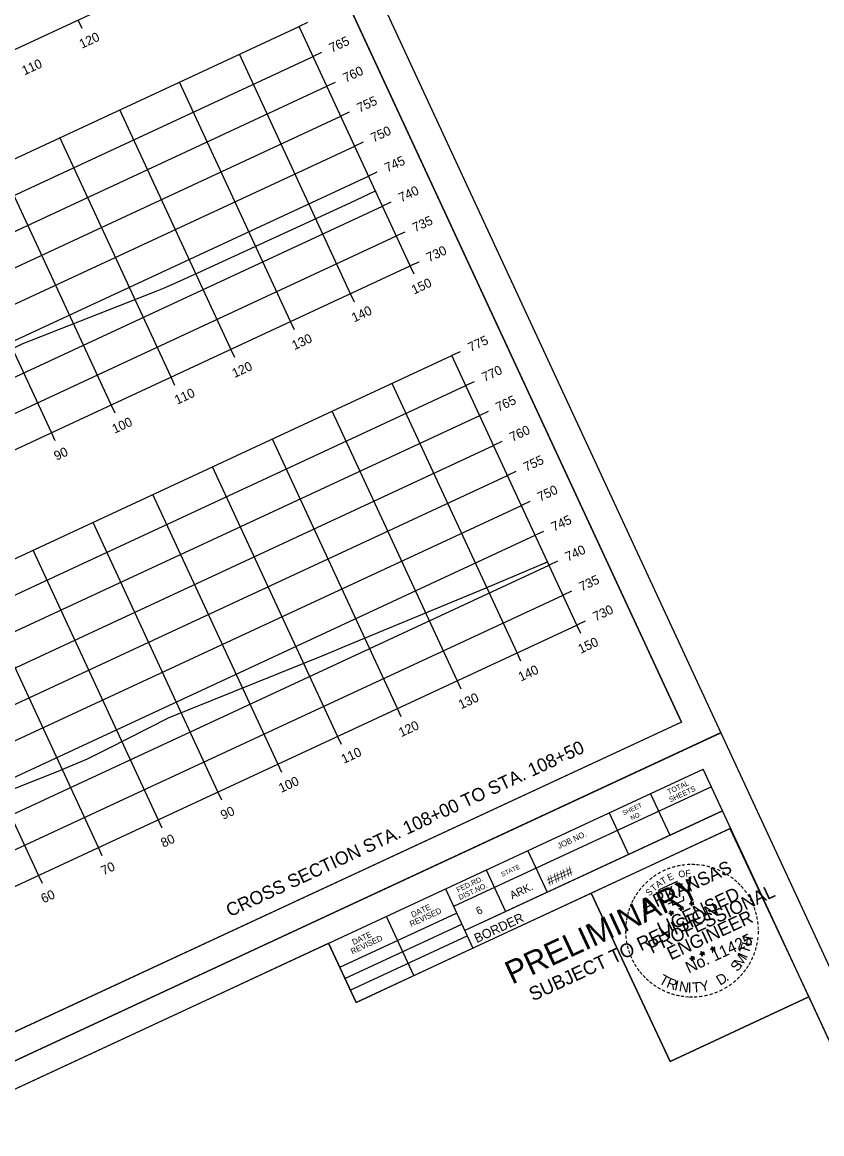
# Model space of a CAD drawing. Extents: x 1354696 to 1366163, y 660729 to 670380.
# Drawn here: x 1355072 to 1355193.2, y 664952.5 to 665120.9 of the extents above; entities that cross this region are included whole.
import ezdxf

# ---------------------------------------------------------------- set-up
doc = ezdxf.new("R2010")
doc.units = 0
for name, color, linetype in [('R_Axis', 7, 'Continuous'), ('R_Axis Annot', 7, 'Continuous'), ('R_Border', 7, 'Continuous'), ('R_Border PE', 7, 'Continuous'), ('R_Border Prem', 7, 'Continuous'), ('R_Draft', 7, 'Continuous'), ('R_Exist Surface', 7, 'Continuous'), ('R_Grid', 7, 'Continuous'), ('R_No Plot', 7, 'Continuous')]:
    doc.layers.add(name, color=color, linetype=linetype)

msp = doc.modelspace()

# ---------------------------------------------------------------- linework, layer by layer
at = {"layer": 'R_Axis'}
for p, q in [((1354835.56, 665007.58), (1355107.67, 665133.91)), ((1355081.05, 665120.01), (1355080.46, 665121.27)), ((1355115.25, 665120.89), (1355113.98, 665120.3)), ((1355130.83, 665084.02), (1355113.98, 665120.3)), ((1355117.36, 665116.36), (1355116.09, 665115.77)), ((1355119.46, 665111.82), (1355118.19, 665111.23)), ((1355121.57, 665107.29), (1355120.3, 665106.7)), ((1355123.68, 665102.75), (1355122.41, 665102.16)), ((1355125.78, 665098.22), (1355124.51, 665097.63)), ((1355127.89, 665093.68), (1355126.62, 665093.09)), ((1355129.99, 665089.15), (1355128.72, 665088.56)), ((1354858.72, 664957.69), (1355130.83, 665084.02)), ((1355132.1, 665084.61), (1355130.83, 665084.02)), ((1355131.42, 665082.75), (1355130.83, 665084.02)), ((1355122.35, 665078.54), (1355121.76, 665079.81)), ((1355113.28, 665074.33), (1355112.69, 665075.6)), ((1355104.21, 665070.12), (1355103.62, 665071.39)), ((1355138.41, 665071.01), (1355137.14, 665070.42)), ((1355156.09, 665029.6), (1355137.14, 665070.42)), ((1355095.14, 665065.91), (1355094.55, 665067.18)), ((1355140.52, 665066.47), (1355139.25, 665065.88)), ((1355086.07, 665061.7), (1355085.48, 665062.97)), ((1355142.63, 665061.94), (1355141.36, 665061.35)), ((1355077, 665057.49), (1355076.41, 665058.76)), ((1355144.73, 665057.4), (1355143.46, 665056.81)), ((1355146.84, 665052.87), (1355145.57, 665052.28)), ((1355148.94, 665048.33), (1355147.67, 665047.74)), ((1355151.05, 665043.8), (1355149.78, 665043.21)), ((1355153.15, 665039.26), (1355151.88, 665038.67)), ((1355155.26, 665034.73), (1355153.99, 665034.14)), ((1354883.99, 664903.27), (1355156.09, 665029.6)), ((1355157.36, 665030.19), (1355156.09, 665029.6)), ((1355156.68, 665028.33), (1355156.09, 665029.6)), ((1355147.61, 665024.12), (1355147.02, 665025.39)), ((1355138.54, 665019.91), (1355137.95, 665021.18)), ((1355129.47, 665015.7), (1355128.88, 665016.97)), ((1355120.4, 665011.49), (1355119.81, 665012.76)), ((1355111.33, 665007.28), (1355110.74, 665008.55)), ((1355102.26, 665003.07), (1355101.67, 665004.34)), ((1355093.19, 664998.85), (1355092.6, 665000.12)), ((1355084.12, 664994.64), (1355083.53, 664995.91)), ((1355075.05, 664990.43), (1355074.46, 664991.7))]:
    msp.add_line(p, q, dxfattribs=at)
at = {"layer": 'R_Border'}
for p, q in [((1355171.94, 665014.91), (1355085.42, 665201.26)), ((1355171.94, 665014.91), (1354885.16, 664881.76)), ((1354888.47, 664874.62), (1355175.25, 665007.76)), ((1355261.77, 664821.41), (1355175.25, 665007.76)), ((1355176.49, 665005.09), (1355137.4, 664986.94)), ((1355167.27, 665004.05), (1355170.19, 664997.76)), ((1355176.48, 665005.11), (1355176.48, 665005.11)), ((1355178.18, 665001.47), (1355139.08, 664983.32)), ((1355141.77, 664984.56), (1355178.18, 665001.47)), ((1355160.98, 665001.13), (1355163.9, 664994.84)), ((1355179.41, 664998.8), (1355122.6, 664972.42)), ((1355148.66, 664995.41), (1355151.58, 664989.12)), ((1355142.36, 664992.49), (1355145.29, 664986.2)), ((1355136.16, 664989.61), (1355140.32, 664980.65)), ((1355120.13, 664977.74), (1355137.85, 664985.96)), ((1355131.38, 664976.5), (1355127.22, 664985.46)), ((1355120.91, 664976.05), (1355138.64, 664984.28)), ((1355121.73, 664974.29), (1355139.45, 664982.52)), ((1355122.6, 664972.42), (1355118.44, 664981.38))]:
    msp.add_line(p, q, dxfattribs=at)
at = {"layer": 'R_Border PE'}
for p, q in [((1355173.17, 664987.35), (1355173.42, 664987.42)), ((1355173.17, 664987.35), (1355173.54, 664987.4)), ((1355173.17, 664987.35), (1355173.44, 664987.34)), ((1355173.54, 664987.4), (1355173.38, 664987.73)), ((1355173.38, 664987.73), (1355173.53, 664987.52)), ((1355173.38, 664987.73), (1355173.45, 664987.48)), ((1355173.47, 664987.04), (1355173.54, 664987.4)), ((1355173.47, 664987.04), (1355173.57, 664987.32)), ((1355173.47, 664987.04), (1355173.48, 664987.31)), ((1355173.8, 664987.64), (1355173.54, 664987.4)), ((1355173.85, 664987.22), (1355173.54, 664987.4)), ((1355173.8, 664987.64), (1355173.57, 664987.48)), ((1355173.85, 664987.22), (1355173.57, 664987.32)), ((1355173.85, 664987.22), (1355173.61, 664987.42)), ((1355173.8, 664987.64), (1355173.66, 664987.46)), ((1355170.05, 664985.91), (1355170.3, 664985.98)), ((1355170.05, 664985.91), (1355170.42, 664985.96)), ((1355170.05, 664985.91), (1355170.32, 664985.9)), ((1355170.42, 664985.96), (1355170.26, 664986.29)), ((1355170.26, 664986.29), (1355170.41, 664986.09)), ((1355170.26, 664986.29), (1355170.33, 664986.05)), ((1355170.35, 664985.6), (1355170.42, 664985.96)), ((1355170.35, 664985.6), (1355170.45, 664985.89)), ((1355170.35, 664985.6), (1355170.36, 664985.88)), ((1355170.68, 664986.21), (1355170.42, 664985.96)), ((1355170.73, 664985.78), (1355170.42, 664985.96)), ((1355170.68, 664986.21), (1355170.45, 664986.04)), ((1355170.73, 664985.78), (1355170.45, 664985.88)), ((1355170.73, 664985.78), (1355170.49, 664985.99)), ((1355170.68, 664986.21), (1355170.54, 664986.03)), ((1355171.57, 664986.62), (1355171.82, 664986.68)), ((1355171.57, 664986.62), (1355171.93, 664986.66)), ((1355171.57, 664986.62), (1355171.83, 664986.61)), ((1355171.93, 664986.66), (1355171.78, 664987)), ((1355171.78, 664987), (1355171.93, 664986.79)), ((1355171.78, 664987), (1355171.85, 664986.75)), ((1355171.86, 664986.3), (1355171.93, 664986.66)), ((1355171.86, 664986.3), (1355171.96, 664986.59)), ((1355171.86, 664986.3), (1355171.87, 664986.58)), ((1355172.2, 664986.91), (1355171.93, 664986.66)), ((1355172.25, 664986.48), (1355171.93, 664986.66)), ((1355172.2, 664986.91), (1355171.96, 664986.75)), ((1355172.25, 664986.48), (1355171.96, 664986.59)), ((1355172.25, 664986.48), (1355172, 664986.69)), ((1355172.2, 664986.91), (1355172.06, 664986.73)), ((1355176.36, 664980.48), (1355176.61, 664980.55)), ((1355176.36, 664980.48), (1355176.72, 664980.53)), ((1355176.36, 664980.48), (1355176.63, 664980.47)), ((1355176.72, 664980.53), (1355176.57, 664980.86)), ((1355176.57, 664980.86), (1355176.72, 664980.65)), ((1355176.57, 664980.86), (1355176.64, 664980.61)), ((1355176.65, 664980.17), (1355176.72, 664980.53)), ((1355176.65, 664980.17), (1355176.75, 664980.45)), ((1355176.65, 664980.17), (1355176.66, 664980.44)), ((1355176.99, 664980.78), (1355176.72, 664980.53)), ((1355177.04, 664980.35), (1355176.72, 664980.53)), ((1355176.99, 664980.78), (1355176.75, 664980.61)), ((1355177.04, 664980.35), (1355176.76, 664980.45)), ((1355177.04, 664980.35), (1355176.79, 664980.55)), ((1355176.99, 664980.78), (1355176.85, 664980.6)), ((1355173.24, 664979.04), (1355173.49, 664979.11)), ((1355173.24, 664979.04), (1355173.6, 664979.09)), ((1355173.24, 664979.04), (1355173.51, 664979.03)), ((1355173.6, 664979.09), (1355173.45, 664979.42)), ((1355173.45, 664979.42), (1355173.6, 664979.22)), ((1355173.45, 664979.42), (1355173.52, 664979.18)), ((1355173.53, 664978.73), (1355173.6, 664979.09)), ((1355173.53, 664978.73), (1355173.63, 664979.02)), ((1355173.53, 664978.73), (1355173.54, 664979)), ((1355173.87, 664979.34), (1355173.6, 664979.09)), ((1355173.92, 664978.91), (1355173.6, 664979.09)), ((1355173.87, 664979.34), (1355173.63, 664979.17)), ((1355173.92, 664978.91), (1355173.64, 664979.01)), ((1355173.92, 664978.91), (1355173.67, 664979.12)), ((1355173.87, 664979.34), (1355173.73, 664979.16)), ((1355174.75, 664979.75), (1355175, 664979.81)), ((1355174.75, 664979.75), (1355175.12, 664979.79)), ((1355174.75, 664979.75), (1355175.02, 664979.74)), ((1355175.12, 664979.79), (1355174.96, 664980.12)), ((1355174.96, 664980.12), (1355175.11, 664979.92)), ((1355174.96, 664980.12), (1355175.03, 664979.88)), ((1355175.04, 664979.43), (1355175.12, 664979.79)), ((1355175.04, 664979.43), (1355175.15, 664979.72)), ((1355175.04, 664979.43), (1355175.06, 664979.71)), ((1355175.38, 664980.04), (1355175.12, 664979.79)), ((1355175.43, 664979.61), (1355175.12, 664979.79)), ((1355175.38, 664980.04), (1355175.15, 664979.88)), ((1355175.43, 664979.61), (1355175.15, 664979.72)), ((1355175.43, 664979.61), (1355175.19, 664979.82)), ((1355175.38, 664980.04), (1355175.24, 664979.86))]:
    msp.add_line(p, q, dxfattribs=at)
for points in [[(1355172.03, 664990.09), (1355172.04, 664990.41), (1355171.43, 664990.1), (1355171.28, 664990.76), (1355168.46, 664989.45)], [(1355168.46, 664989.45), (1355169.05, 664988.81)], [(1355169.92, 664987.46), (1355169.96, 664987.38), (1355170.48, 664987.6), (1355170.63, 664987.15), (1355172.33, 664987.94), (1355172.28, 664988.51)], [(1355173.38, 664987.73), (1355173.85, 664987.22), (1355173.17, 664987.35), (1355173.8, 664987.64), (1355173.47, 664987.04), (1355173.38, 664987.73)], [(1355170.26, 664986.29), (1355170.73, 664985.78), (1355170.05, 664985.91), (1355170.68, 664986.21), (1355170.35, 664985.6), (1355170.26, 664986.29)], [(1355171.78, 664987), (1355172.25, 664986.48), (1355171.57, 664986.62), (1355172.2, 664986.91), (1355171.86, 664986.3), (1355171.78, 664987)], [(1355176.57, 664980.86), (1355177.04, 664980.35), (1355176.36, 664980.48), (1355176.99, 664980.78), (1355176.65, 664980.17), (1355176.57, 664980.86)], [(1355173.45, 664979.42), (1355173.92, 664978.91), (1355173.24, 664979.04), (1355173.87, 664979.34), (1355173.53, 664978.73), (1355173.45, 664979.42)], [(1355174.96, 664980.12), (1355175.43, 664979.61), (1355174.75, 664979.75), (1355175.38, 664980.04), (1355175.04, 664979.43), (1355174.96, 664980.12)]]:
    msp.add_lwpolyline(points, dxfattribs=at)
for centre, radius in [((1355173.54, 664987.39), 0.172), ((1355173.54, 664987.39), 0.145), ((1355173.54, 664987.39), 0.116), ((1355173.54, 664987.39), 0.0991), ((1355173.54, 664987.39), 0.0747), ((1355173.54, 664987.39), 0.0495), ((1355173.54, 664987.39), 0.0296), ((1355170.42, 664985.96), 0.172), ((1355170.42, 664985.96), 0.145), ((1355170.42, 664985.96), 0.116), ((1355170.42, 664985.96), 0.0991), ((1355170.42, 664985.96), 0.0747), ((1355170.42, 664985.96), 0.0495), ((1355170.42, 664985.96), 0.0296), ((1355171.93, 664986.66), 0.172), ((1355171.93, 664986.66), 0.145), ((1355171.93, 664986.66), 0.116), ((1355171.93, 664986.66), 0.0991), ((1355171.93, 664986.66), 0.0747), ((1355171.93, 664986.66), 0.0495), ((1355171.93, 664986.66), 0.0296), ((1355176.72, 664980.53), 0.172), ((1355176.72, 664980.53), 0.145), ((1355176.72, 664980.53), 0.116), ((1355176.72, 664980.53), 0.0991), ((1355176.72, 664980.53), 0.0747), ((1355176.72, 664980.53), 0.0495), ((1355176.72, 664980.53), 0.0296), ((1355173.6, 664979.09), 0.172), ((1355173.6, 664979.09), 0.145), ((1355173.6, 664979.09), 0.116), ((1355173.6, 664979.09), 0.0991), ((1355173.6, 664979.09), 0.0747), ((1355173.6, 664979.09), 0.0495), ((1355173.6, 664979.09), 0.0296), ((1355175.12, 664979.79), 0.172), ((1355175.12, 664979.79), 0.145), ((1355175.12, 664979.79), 0.116), ((1355175.12, 664979.79), 0.0991), ((1355175.12, 664979.79), 0.0747), ((1355175.12, 664979.79), 0.0495), ((1355175.12, 664979.79), 0.0296)]:
    msp.add_circle(centre, radius, dxfattribs=at)
at = {"layer": 'R_Exist Surface'}
for points in [[(1355065.58, 665069.08), (1355072, 665072.23), (1355092.29, 665080.17), (1355093.33, 665080.62), (1355094.9, 665081.3), (1355098.63, 665082.98), (1355121.73, 665093.6), (1355125.56, 665095.37)], [(1355068.08, 665003.77), (1355077.17, 665007.36), (1355081.88, 665009.33), (1355085.03, 665010.88), (1355094.28, 665015.58), (1355117.46, 665024.96), (1355121.54, 665026.63), (1355142.36, 665035.25), (1355151.65, 665039.16)]]:
    msp.add_lwpolyline(points, dxfattribs=at)
at = {"layer": 'R_Grid'}
for p, q in [((1354835.56, 665007.58), (1355107.67, 665133.91)), ((1354841.88, 664993.97), (1355113.98, 665120.3)), ((1355130.83, 665084.02), (1355113.98, 665120.3)), ((1354843.99, 664989.44), (1355116.09, 665115.77)), ((1355121.76, 665079.81), (1355104.91, 665116.09)), ((1355112.69, 665075.6), (1355095.84, 665111.88)), ((1354846.09, 664984.9), (1355118.19, 665111.23)), ((1355103.62, 665071.39), (1355086.77, 665107.67)), ((1354848.2, 664980.37), (1355120.3, 665106.7)), ((1355094.55, 665067.18), (1355077.7, 665103.46)), ((1354850.3, 664975.83), (1355122.41, 665102.16)), ((1355085.48, 665062.97), (1355068.63, 665099.25)), ((1354852.41, 664971.3), (1355124.51, 665097.63)), ((1355076.41, 665058.76), (1355059.56, 665095.04)), ((1354854.51, 664966.76), (1355126.62, 665093.09)), ((1354856.62, 664962.23), (1355128.72, 665088.56)), ((1354858.72, 664957.69), (1355130.83, 665084.02)), ((1354865.04, 664944.09), (1355137.14, 665070.42)), ((1355156.09, 665029.6), (1355137.14, 665070.42)), ((1354867.15, 664939.55), (1355139.25, 665065.88)), ((1355147.02, 665025.39), (1355128.07, 665066.21)), ((1354869.25, 664935.02), (1355141.36, 665061.35)), ((1355137.95, 665021.18), (1355119, 665061.99)), ((1354871.36, 664930.48), (1355143.46, 665056.81)), ((1355128.88, 665016.97), (1355109.93, 665057.78)), ((1355119.81, 665012.76), (1355100.86, 665053.57)), ((1354873.46, 664925.95), (1355145.57, 665052.28)), ((1355110.74, 665008.55), (1355091.79, 665049.36)), ((1354875.57, 664921.41), (1355147.67, 665047.74)), ((1355101.67, 665004.34), (1355082.72, 665045.15)), ((1354877.67, 664916.88), (1355149.78, 665043.21)), ((1355092.6, 665000.12), (1355073.65, 665040.94)), ((1354879.78, 664912.34), (1355151.88, 665038.67)), ((1355083.53, 664995.91), (1355064.58, 665036.73)), ((1354881.88, 664907.81), (1355153.99, 665034.14)), ((1355074.46, 664991.7), (1355055.51, 665032.52)), ((1354883.99, 664903.27), (1355156.09, 665029.6))]:
    msp.add_line(p, q, dxfattribs=at)
at = {"layer": 'R_No Plot'}
for p, q in [((1354875.58, 664872.93), (1355177.92, 665013.3)), ((1354875.59, 664872.93), (1355177.92, 665013.29)), ((1355167.13, 664968.34), (1355167.13, 664968.34))]:
    msp.add_line(p, q, dxfattribs=at)
for points in [[(1354785.74, 665066.42), (1355088.09, 665206.79), (1355177.92, 665013.29), (1354875.58, 664872.92)], [(1355010.8, 665166.62), (1355028.6, 665174.88), (1355032.76, 665165.92), (1355047.37, 665172.71), (1355068.42, 665182.48), (1355080.38, 665156.99), (1355101.43, 665166.76), (1355171.94, 665014.91), (1354885.16, 664881.76), (1354798.64, 665068.12)], [(1354875.58, 664872.92), (1355177.92, 665013.29), (1355267.76, 664819.79), (1354965.42, 664679.42)], [(1355158.25, 664988.98), (1355179.3, 664998.75), (1355191.27, 664973.26), (1355170.22, 664963.49)], [(1355100.64, 664973.12), (1355118.44, 664981.38), (1355122.6, 664972.42), (1355137.21, 664979.21), (1355158.25, 664988.98), (1355170.22, 664963.49), (1355191.27, 664973.26), (1355261.77, 664821.41), (1354974.99, 664688.26), (1354888.47, 664874.62)]]:
    msp.add_lwpolyline(points, close=True, dxfattribs=at)

# ---------------------------------------------------------------- texts
at = {"layer": 'R_Axis Annot'}
for s, p in [('120', (1355081.03, 665116.91)), ('765', (1355118.92, 665116.31)), ('110', (1355072.32, 665112.87)), ('760', (1355121.03, 665111.78)), ('755', (1355123.13, 665107.24)), ('750', (1355125.24, 665102.71)), ('745', (1355127.35, 665098.17)), ('740', (1355129.45, 665093.64)), ('735', (1355131.56, 665089.1)), ('730', (1355133.66, 665084.57)), ('150', (1355131.4, 665079.66)), ('140', (1355122.33, 665075.45)), ('130', (1355113.26, 665071.24)), ('775', (1355139.98, 665070.96)), ('120', (1355104.19, 665067.02)), ('770', (1355142.08, 665066.43)), ('110', (1355095.48, 665062.98)), ('765', (1355144.19, 665061.89)), ('100', (1355086, 665058.58)), ('760', (1355146.3, 665057.36)), ('90', (1355077.19, 665054.49)), ('755', (1355148.4, 665052.82)), ('750', (1355150.51, 665048.29)), ('745', (1355152.61, 665043.75)), ('740', (1355154.72, 665039.22)), ('735', (1355156.82, 665034.68)), ('730', (1355158.93, 665030.15)), ('150', (1355156.67, 665025.24)), ('140', (1355147.6, 665021.03)), ('130', (1355138.53, 665016.82)), ('120', (1355129.46, 665012.6)), ('110', (1355120.75, 665008.56)), ('100', (1355111.27, 665004.16)), ('90', (1355102.46, 665000.07)), ('80', (1355093.39, 664995.86)), ('70', (1355084.32, 664991.65)), ('60', (1355075.22, 664987.42))]:
    msp.add_text(s, height=1.4, rotation=24.9042, dxfattribs=at).set_placement(p)
at = {"layer": 'R_Border'}
for s, height, p in [('TOTAL', 0.782, (1355170.02, 665003.92)), ('SHEETS', 0.782, (1355170.27, 665002.73)), ('SHEET', 0.684, (1355163.2, 665000.75)), ('NO.', 0.684, (1355164.41, 665000.01)), ('JOB NO.', 0.879, (1355153.39, 664995.67)), ('STATE', 0.684, (1355144.79, 664991.45)), ('####', 1.4, (1355151.9, 664990.08)), ('FED.RD.', 0.782, (1355138.04, 664989.07)), ('DIST.NO.', 0.782, (1355138.36, 664987.92)), ('ARK.', 1.172, (1355146.26, 664988.04)), ('DATE', 0.879, (1355131.19, 664985.25)), ('REVISED', 0.879, (1355130.98, 664983.85)), ('BORDER', 1.4, (1355140.92, 664981.4)), ('6', 1.17, (1355141.13, 664985.65)), ('REVISED', 0.879, (1355122.04, 664979.7)), ('DATE', 0.879, (1355122.25, 664981.1))]:
    msp.add_text(s, height=height, rotation=24.9042, dxfattribs=at).set_placement(p)
at = {"layer": 'R_Border PE'}
for s, height, rotation, p in [('ARKANSAS', 2, 24.9042, (1355166.57, 664986.05)), ('-', 1.6, 30.801, (1355168.59, 664991.32)), ('-', 1.6, 25.0904, (1355169.26, 664991.71)), ('-', 1.6, 22.6472, (1355169.92, 664992)), ('-', 1.6, 17.0659, (1355170.62, 664992.26)), ('-', 1.6, 12.1091, (1355171.32, 664992.46)), ('O', 1, 15.3557, (1355171.63, 664991.28)), ('-', 1.6, 7.2404, (1355171.96, 664992.59)), ('F', 1, 4.9748, (1355172.59, 664991.48)), ('-', 1.6, 2.7593, (1355172.72, 664992.7)), ('-', 1.6, 359.0253, (1355173.41, 664992.72)), ('-', 1.6, 354.5451, (1355174.05, 664992.7)), ('-', 1.6, 350.7668, (1355174.79, 664992.65)), ('-', 1.6, 345.4339, (1355175.52, 664992.52)), ('-', 1.6, 340.4828, (1355176.27, 664992.33)), ('-', 1.6, 334.7839, (1355177.01, 664992.07)), ('-', 1.6, 331.5563, (1355177.74, 664991.74)), ('-', 1.6, 44.0802, (1355166.85, 664989.94)), ('-', 1.6, 38.5343, (1355167.43, 664990.48)), ('-', 1.6, 35.1235, (1355167.97, 664990.91)), ('A', 1, 36.1173, (1355168.43, 664989.73)), ('T', 1, 30.9269, (1355169.13, 664990.23)), ('E', 1, 25.7365, (1355170.09, 664990.8)), ('-', 1.4, 328.5795, (1355178.42, 664991.43)), ('-', 1.6, 324.5725, (1355178.97, 664991.02)), ('-', 1.6, 319.567, (1355179.52, 664990.6)), ('-', 1.6, 315.477, (1355180, 664990.18)), ('-', 1.6, 58.9677, (1355165.56, 664988.29)), ('-', 1.6, 53.696, (1355165.94, 664988.88)), ('-', 1.6, 49.2114, (1355166.39, 664989.43)), ('S', 1, 46.4982, (1355167.1, 664988.46)), ('PROFESSIONAL', 2, 24.9042, (1355167.46, 664979.79)), ('T', 1, 41.3078, (1355167.79, 664989.15)), ('LICENSED', 2, 24.9042, (1355168.86, 664982.54)), ('-', 1.6, 310.0274, (1355180.45, 664989.76)), ('-', 1.6, 305.4535, (1355180.95, 664989.17)), ('-', 1.6, 301.5003, (1355181.42, 664988.54)), ('-', 1.6, 67.8664, (1355164.71, 664986.59)), ('-', 1.6, 63.8548, (1355164.93, 664987.15)), ('-', 1.6, 61.1359, (1355165.2, 664987.69)), ('DWB', 0.01, 24.9042, (1355173.53, 664987.39)), ('-', 1.6, 299.2343, (1355181.78, 664987.91)), ('-', 1.6, 294.8448, (1355182.07, 664987.35)), ('-', 1.6, 75.5183, (1355164.35, 664985.35)), ('-', 1.6, 73.3272, (1355164.51, 664985.96)), ('ENGINEER', 2, 24.9042, (1355170.34, 664978.78)), ('DWB', 0.01, 24.9042, (1355170.41, 664985.95)), ('DWB', 0.01, 24.9042, (1355171.92, 664986.65)), ('-', 1.6, 288.4214, (1355182.34, 664986.74)), ('-', 1.6, 285.8995, (1355182.55, 664986.11)), ('-', 1.6, 280.6668, (1355182.73, 664985.45)), ('-', 1.6, 87.7755, (1355164.11, 664983.36)), ('-', 1.6, 82.9748, (1355164.14, 664984.05)), ('-', 1.6, 79.1366, (1355164.21, 664984.67)), ('-', 1.6, 277.7723, (1355182.87, 664984.72)), ('-', 1.6, 272.7928, (1355182.95, 664984.02)), ('-', 1.6, 92.6784, (1355164.13, 664982.7)), ('-', 1.6, 97.2986, (1355164.2, 664982.04)), ('No. 11425', 1.757, 24.9042, (1355173.06, 664976.79)), ('H', 1.54, 79.513, (1355182.55, 664980.9)), ('-', 1.6, 263.9754, (1355182.94, 664982.49)), ('-', 1.6, 269.5239, (1355182.98, 664983.34)), ('-', 1.6, 100.3651, (1355164.32, 664981.3)), ('-', 1.6, 106.1054, (1355164.5, 664980.6)), ('DWB', 0.01, 24.9042, (1355176.71, 664980.52)), ('T', 1.54, 71.5486, (1355182.14, 664979.67)), ('-', 1.6, 256.1579, (1355182.7, 664981.03)), ('-', 1.6, 258.7494, (1355182.85, 664981.73)), ('-', 1.6, 110.0905, (1355164.73, 664979.94)), ('-', 1.6, 113.9664, (1355165, 664979.3)), ('-', 1.6, 119.1, (1355165.33, 664978.65)), ('DWB', 0.01, 24.9042, (1355173.59, 664979.08)), ('DWB', 0.01, 24.9042, (1355175.11, 664979.78)), ('S', 1.54, 51.8354, (1355180.44, 664976.97)), ('M', 1.54, 57.5605, (1355181.03, 664977.69)), ('I', 1.54, 67.0178, (1355181.83, 664979)), ('-', 1.6, 245.9893, (1355182.24, 664979.64)), ('-', 1.6, 250.6695, (1355182.5, 664980.32)), ('-', 1.6, 123.8521, (1355165.68, 664978.08)), ('-', 1.6, 126.6191, (1355166.11, 664977.47)), ('-', 1.6, 130.362, (1355166.51, 664977)), ('-', 1.6, 232.261, (1355181.26, 664977.86)), ('-', 1.6, 237.1533, (1355181.62, 664978.4)), ('-', 1.6, 240.6405, (1355181.94, 664978.98)), ('-', 1.6, 133.9916, (1355166.97, 664976.52)), ('-', 1.6, 138.9685, (1355167.45, 664976.09)), ('-', 1.6, 140.633, (1355167.99, 664975.65)), ('T', 1.54, 330.9447, (1355168.43, 664975.41)), ('R', 1.54, 338.9091, (1355169.56, 664974.78)), ('I', 1.54, 346.8735, (1355170.77, 664974.31)), ('N', 1.54, 351.4044, (1355171.49, 664974.12)), ('I', 1.54, 0.2645, (1355172.91, 664973.92)), ('T', 1.54, 4.7953, (1355173.65, 664973.9)), ('Y', 1.54, 12.7597, (1355174.94, 664974.01)), ('D', 1.54, 31.3011, (1355177.8, 664974.94)), ('.', 1.54, 38.6683, (1355178.83, 664975.56)), ('-', 1.6, 220.3785, (1355179.87, 664976.29)), ('-', 1.6, 225.6226, (1355180.38, 664976.8)), ('-', 1.6, 229.1558, (1355180.83, 664977.3)), ('-', 1.6, 145.3513, (1355168.56, 664975.27)), ('-', 1.6, 150.7976, (1355169.16, 664974.93)), ('-', 1.6, 155.6223, (1355169.81, 664974.63)), ('-', 1.6, 159.128, (1355170.51, 664974.35)), ('-', 1.6, 163.838, (1355171.18, 664974.15)), ('-', 1.6, 198.0196, (1355176.61, 664974.37)), ('-', 1.6, 201.4224, (1355177.31, 664974.63)), ('-', 1.6, 206.4959, (1355177.98, 664974.96)), ('-', 1.6, 210.7208, (1355178.68, 664975.37)), ('-', 1.6, 216.1899, (1355179.29, 664975.8)), ('-', 1.6, 169.5505, (1355171.86, 664974.02)), ('-', 1.6, 172.9939, (1355172.52, 664973.92)), ('-', 1.6, 176.4746, (1355173.18, 664973.86)), ('-', 1.6, 179.5044, (1355173.76, 664973.86)), ('-', 1.6, 183.4654, (1355174.43, 664973.89)), ('-', 1.6, 187.7024, (1355175.15, 664973.99)), ('-', 1.6, 192.4597, (1355175.87, 664974.14))]:
    msp.add_text(s, height=height, rotation=rotation, dxfattribs=at).set_placement(p)
at = {"layer": 'R_Border Prem'}
for s, height, p in [('PRELIMINARY', 3.5, (1355146.26, 664975.1)), ('SUBJECT TO REVISION', 2.0751, (1355149.43, 664972.57)), ('DWB', 0.01, (1355146.16, 664977.09))]:
    msp.add_text(s, height=height, rotation=24.9042, dxfattribs=at).set_placement(p)
at = {"layer": 'R_Draft'}
msp.add_text('CROSS SECTION STA. 108+00 TO STA. 108+50', height=2, rotation=24.9042, dxfattribs=at).set_placement((1355103.48, 664985.33))

doc.saveas('drawing.dxf')
